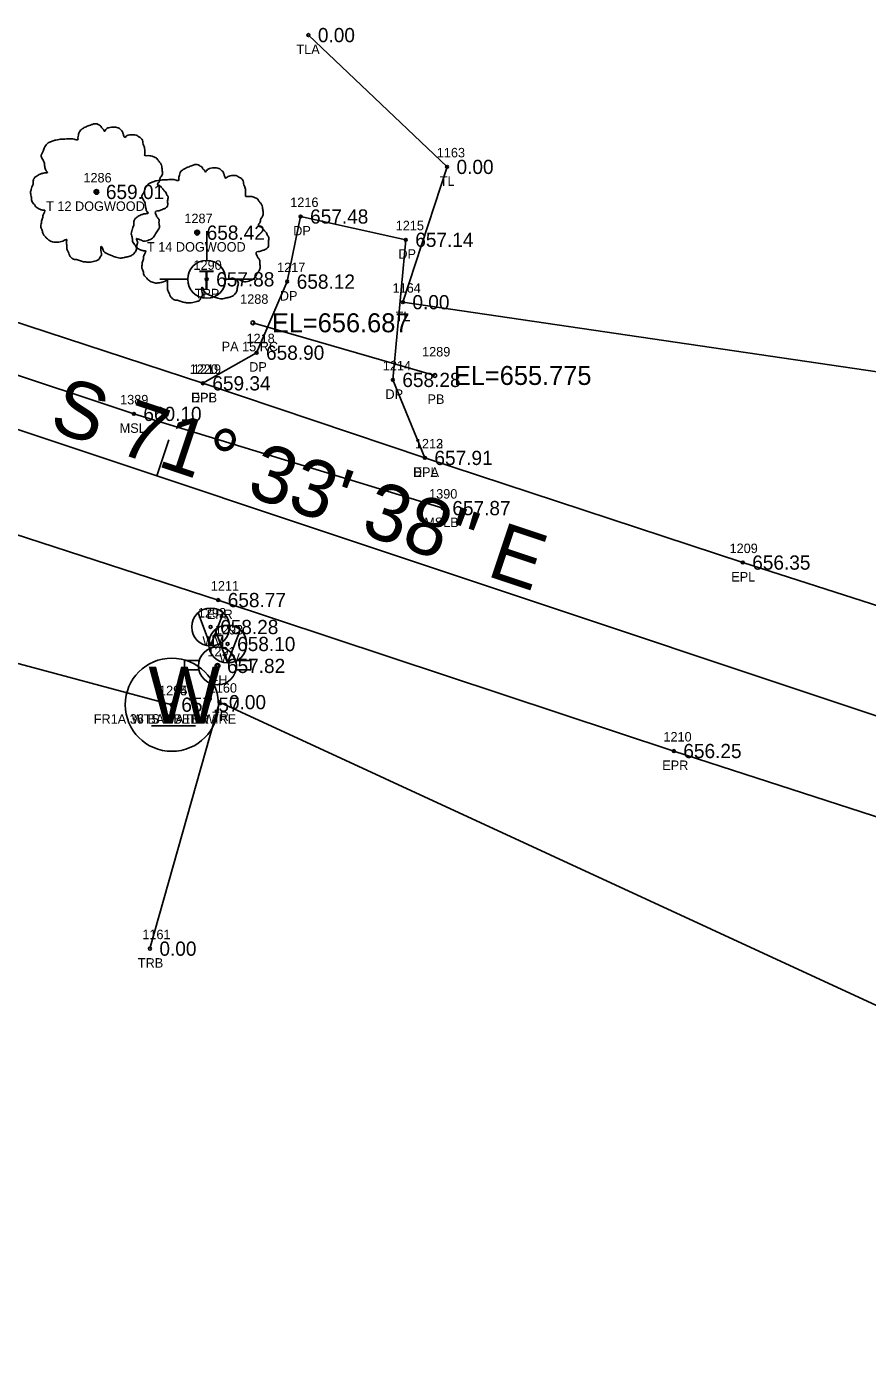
# Model space of a CAD drawing. Extents: x 1655137 to 1657928, y 1003994 to 1005407.
# Drawn here: x 1656260.6 to 1656349.2, y 1004565 to 1004705.8 of the extents above; entities that cross this region are included whole.
import ezdxf

# ---------------------------------------------------------------- set-up
doc = ezdxf.new("R2010")
doc.units = 0
for name, color, linetype in [('RD_EX_DR_Pipe', 7, 'Continuous'), ('RD_EX_DR_Pipe_txCode', 7, 'Continuous'), ('RD_EX_Driveway', 7, 'Continuous'), ('RD_EX_Driveway_txCode', 7, 'Continuous'), ('RD_EX_Fence_Other', 7, 'Continuous'), ('RD_EX_Fence_Other_txCode', 7, 'Continuous'), ('RD_EX_Misc', 7, 'Continuous'), ('RD_EX_Misc_txCode', 7, 'Continuous'), ('RD_EX_Road', 7, 'Continuous'), ('RD_EX_Road_txCode', 7, 'Continuous'), ('RD_EX_TX_Driveway_ELEV', 7, 'Continuous'), ('RD_EX_TX_Fence_Other_ELEV', 7, 'Continuous'), ('RD_EX_TX_Misc_ELEV', 7, 'Continuous'), ('RD_EX_TX_Road_ELEV', 7, 'Continuous'), ('RD_EX_TX_UT_ELEV', 7, 'Continuous'), ('RD_EX_TX_VEG_ELEV', 7, 'Continuous'), ('RD_EX_UT', 7, 'Continuous'), ('RD_EX_UT_txCode', 7, 'Continuous'), ('RD_EX_VEG', 7, 'Continuous'), ('RD_EX_VEG_txCode', 7, 'Continuous'), ('RD_HC_Cl', 7, 'Continuous'), ('RD_HC_Data', 7, 'Continuous'), ('RD_HC_Data_Tic', 7, 'Continuous'), ('RD_SMD_Locator', 7, 'Continuous'), ('RD_TX_Pipe_ElevEX', 7, 'Continuous')]:
    doc.layers.add(name, color=color, linetype=linetype)

msp = doc.modelspace()

# ---------------------------------------------------------------- linework, layer by layer
at = {"layer": 'RD_EX_DR_Pipe'}
msp.add_line((1656284.42, 1004674.61), (1656303.6, 1004669.06), dxfattribs=at)
at = {"layer": 'RD_EX_Driveway'}
msp.add_lwpolyline([(1656302.55, 1004660.37), (1656299.17, 1004668.59), (1656300.53, 1004683.36), (1656289.45, 1004685.81), (1656288.04, 1004678.95), (1656284.81, 1004671.46), (1656279.15, 1004668.23)], dxfattribs=at)
at = {"layer": 'RD_EX_Fence_Other'}
msp.add_line((1656275.88, 1004634.36), (1656245.21, 1004642.54), dxfattribs=at)
at = {"layer": 'RD_EX_Misc'}
msp.add_lwpolyline([(1655875.57, 1004783.81), (1655899.12, 1004775.73), (1655924.14, 1004767.92), (1655957.49, 1004756.44), (1655982.24, 1004748.48), (1656011.78, 1004739.5), (1656033.16, 1004732.17), (1656057.84, 1004724.63), (1656091.05, 1004714.31), (1656106.3, 1004710.84), (1656119.06, 1004707.85), (1656127.53, 1004711.03), (1656137.41, 1004709.54), (1656150.27, 1004705.03), (1656164.33, 1004699.6), (1656171.58, 1004694.85), (1656180.97, 1004693.87), (1656197.98, 1004688.49), (1656215.11, 1004682.58), (1656240.68, 1004675.39), (1656271.88, 1004665.01), (1656304.44, 1004655.08)], dxfattribs=at)
at = {"layer": 'RD_EX_Road'}
for points in [[(1656365.12, 1004639.99), (1656336.04, 1004649.34), (1656302.55, 1004660.37), (1656279.15, 1004668.23), (1656240.07, 1004681.05), (1656188.23, 1004698.03), (1656166.72, 1004705.51), (1656141.16, 1004714.06), (1656093.11, 1004730.11), (1656044.16, 1004746.75), (1655996.36, 1004762.45), (1655947.2, 1004778.68), (1655899.09, 1004794.03), (1655850.62, 1004809.99), (1655801.91, 1004826.1), (1655753.09, 1004842.31), (1655704.25, 1004858.1)], [(1656358.5, 1004619.83), (1656328.78, 1004629.48), (1656280.77, 1004645.39), (1656247.66, 1004656.11), (1656244.5, 1004656.52), (1656222.03, 1004663.57), (1656217.65, 1004665.96), (1656183.42, 1004677.32), (1656134.59, 1004693.72), (1656086.19, 1004709.75), (1656037.58, 1004726.13), (1655989.57, 1004741.99), (1655940.62, 1004757.88), (1655892.37, 1004773.61), (1655843.48, 1004789.36), (1655805.73, 1004801.4), (1655779.22, 1004810.43), (1655768.8, 1004813.1), (1655744.59, 1004822.13), (1655698.83, 1004837.65)]]:
    msp.add_lwpolyline(points, dxfattribs=at)
at = {"layer": 'RD_EX_UT'}
for p, q in [((1656279.55, 1004684.26), (1656279.55, 1004681.19)), ((1656274.62, 1004679.21), (1656277.55, 1004679.21)), ((1656281.55, 1004679.21), (1656284.62, 1004679.21)), ((1656279.97, 1004640.55), (1656278.67, 1004644.04)), ((1656279.97, 1004640.55), (1656281.29, 1004644)), ((1656280.23, 1004641.67), (1656280.23, 1004640.39)), ((1656281.23, 1004641.67), (1656280.23, 1004641.67)), ((1656281.76, 1004638.77), (1656280.46, 1004642.25)), ((1656281.23, 1004640.37), (1656281.23, 1004641.67)), ((1656281.76, 1004638.77), (1656283.08, 1004642.21)), ((1656278.77, 1004639.02), (1656277.21, 1004639.02)), ((1656277.21, 1004639.02), (1656277.21, 1004638.02)), ((1656284.21, 1004639.02), (1656282.6, 1004639.02)), ((1656284.21, 1004638.02), (1656284.21, 1004639.02)), ((1656277.21, 1004638.02), (1656278.73, 1004638.02)), ((1656282.64, 1004638.02), (1656284.21, 1004638.02)), ((1656273.75, 1004632.15), (1656278.38, 1004632.15))]:
    msp.add_line(p, q, dxfattribs=at)
for centre, radius in [((1656279.55, 1004679.19), 2), ((1656279.97, 1004642.55), 2), ((1656281.76, 1004640.76), 2), ((1656280.69, 1004638.45), 2), ((1656275.88, 1004634.36), 4.91), ((1656280.69, 1004638.45), 0.25)]:
    msp.add_circle(centre, radius, dxfattribs=at)
for start, end in [(74.2455, 103.2128), (163.3387, 192.315), (347.685, 16.6613)]:
    msp.add_arc((1656280.69, 1004638.45), 2, start, end, dxfattribs=at)
at = {"layer": 'RD_EX_VEG'}
for points in [[(1656290.27, 1004704.93), (1656304.88, 1004691.04), (1656300.23, 1004676.78), (1656393.98, 1004663.01), (1656541.61, 1004613.06), (1656540.34, 1004645.89)], [(1656891.08, 1004405.37), (1656915.13, 1004420.4), (1656763.49, 1004475.48), (1656570, 1004542.2), (1656467.82, 1004565.09), (1656367.55, 1004594.62), (1656280.9, 1004634.63), (1656273.57, 1004608.65)]]:
    msp.add_lwpolyline(points, dxfattribs=at)
for centre, radius in [((1656267.93, 1004688.4), 0.25), ((1656267.91, 1004688.38), 0.0001), ((1656278.55, 1004684.11), 0.25), ((1656278.54, 1004684.09), 0.0001)]:
    msp.add_circle(centre, radius, dxfattribs=at)
for points in [[(1656268.06, 1004695.57), (1656267.76, 1004695.59), (1656267.43, 1004695.49), (1656267.18, 1004695.39), (1656266.96, 1004695.32), (1656266.73, 1004695.22), (1656266.43, 1004695.04), (1656266.21, 1004694.84), (1656266.08, 1004694.59), (1656266.03, 1004694.37), (1656265.98, 1004694.09), (1656265.98, 1004693.92), (1656265.86, 1004693.89), (1656265.71, 1004693.92), (1656265.46, 1004693.99), (1656265.21, 1004693.99), (1656264.96, 1004693.99), (1656264.61, 1004693.97), (1656264.26, 1004693.97), (1656263.98, 1004693.92), (1656263.66, 1004693.87), (1656263.28, 1004693.74), (1656262.93, 1004693.62), (1656262.63, 1004693.37), (1656262.38, 1004692.89), (1656262.26, 1004692.54), (1656262.11, 1004692.29), (1656262.26, 1004691.84), (1656262.43, 1004691.49), (1656262.46, 1004691.29), (1656262.53, 1004690.87), (1656262.63, 1004690.64), (1656262.76, 1004690.44), (1656262.68, 1004690.42), (1656262.31, 1004690.37), (1656262.01, 1004690.27), (1656261.58, 1004690.04), (1656261.36, 1004689.82), (1656261.26, 1004689.49), (1656261.24, 1004689.14), (1656261.14, 1004688.94), (1656261.06, 1004688.67), (1656261.04, 1004688.59), (1656260.99, 1004688.27), (1656261.09, 1004687.82), (1656261.11, 1004687.47), (1656261.24, 1004687.24), (1656261.39, 1004687.07), (1656261.56, 1004686.82), (1656261.96, 1004686.59), (1656262.28, 1004686.49), (1656262.48, 1004686.47), (1656262.31, 1004685.97), (1656262.26, 1004685.62), (1656262.13, 1004685.22), (1656262.13, 1004685.15), (1656262.08, 1004684.67), (1656262.23, 1004684.35), (1656262.31, 1004683.97), (1656262.48, 1004683.75), (1656262.76, 1004683.45), (1656263.08, 1004683.22), (1656263.58, 1004683.1), (1656263.98, 1004683.12), (1656264.56, 1004683.3), (1656264.81, 1004683.37), (1656264.78, 1004683.2), (1656264.81, 1004682.82), (1656264.81, 1004682.4), (1656264.96, 1004682.07), (1656265.06, 1004681.8), (1656265.21, 1004681.55), (1656265.53, 1004681.32), (1656265.93, 1004681.25), (1656266.36, 1004681.1), (1656266.81, 1004681.02), (1656267.31, 1004681), (1656267.91, 1004681.15), (1656268.18, 1004681.27), (1656268.28, 1004681.45), (1656268.48, 1004681.82), (1656268.43, 1004682.05), (1656268.46, 1004682.65), (1656268.56, 1004682.47), (1656268.73, 1004682.12), (1656269.23, 1004681.82), (1656269.63, 1004681.65), (1656270.11, 1004681.5), (1656270.41, 1004681.42), (1656270.88, 1004681.5), (1656271.26, 1004681.57), (1656271.63, 1004681.7), (1656271.93, 1004681.97), (1656272.11, 1004682.25), (1656272.16, 1004682.52), (1656272.23, 1004682.9), (1656272.28, 1004683.07)], [(1656272.28, 1004683.07), (1656272.21, 1004683.25), (1656272.16, 1004683.5), (1656272.23, 1004683.47), (1656272.41, 1004683.42), (1656272.68, 1004683.3), (1656272.91, 1004683.22), (1656273.23, 1004683.25), (1656273.5, 1004683.35), (1656273.95, 1004683.62), (1656274.23, 1004684.1), (1656274.5, 1004684.5), (1656274.58, 1004684.82), (1656274.53, 1004685.05), (1656274.5, 1004685.54), (1656274.3, 1004685.79), (1656274.25, 1004685.92), (1656274.15, 1004686.32), (1656274.23, 1004686.37), (1656274.5, 1004686.42), (1656274.88, 1004686.54), (1656275.15, 1004686.67), (1656275.38, 1004686.84), (1656275.45, 1004687.07), (1656275.43, 1004687.47), (1656275.48, 1004687.87), (1656275.4, 1004688.02), (1656275.3, 1004688.17), (1656275.23, 1004688.37), (1656275.08, 1004688.52), (1656274.98, 1004688.67), (1656274.88, 1004688.77), (1656274.75, 1004688.92), (1656274.58, 1004689.04), (1656274.43, 1004689.09), (1656274.38, 1004689.24), (1656274.53, 1004689.44), (1656274.58, 1004689.54), (1656274.6, 1004689.77), (1656274.83, 1004690.12), (1656274.88, 1004690.52), (1656274.83, 1004690.94), (1656274.78, 1004691.22), (1656274.63, 1004691.49), (1656274.43, 1004691.74), (1656274.3, 1004691.92), (1656274.13, 1004692.04), (1656273.8, 1004692.17), (1656273.55, 1004692.22), (1656273.2, 1004692.22), (1656273, 1004692.27), (1656273.03, 1004692.32), (1656273.03, 1004692.47), (1656273.03, 1004692.74), (1656272.95, 1004693.19), (1656272.81, 1004693.69), (1656272.81, 1004693.72), (1656272.71, 1004693.97), (1656272.48, 1004694.17), (1656272.31, 1004694.27), (1656272.11, 1004694.39), (1656271.86, 1004694.42), (1656271.56, 1004694.42), (1656271.28, 1004694.37), (1656271.08, 1004694.27), (1656270.91, 1004694.14), (1656270.83, 1004694.29), (1656270.73, 1004694.59), (1656270.68, 1004694.74), (1656270.53, 1004694.92), (1656270.31, 1004695.12), (1656269.86, 1004695.24), (1656269.23, 1004695.17), (1656268.93, 1004694.97), (1656268.78, 1004694.79), (1656268.73, 1004694.92), (1656268.53, 1004695.12), (1656268.43, 1004695.29), (1656268.26, 1004695.42), (1656268.11, 1004695.52), (1656268.01, 1004695.57)], [(1656278.68, 1004691.27), (1656278.38, 1004691.3), (1656278.06, 1004691.2), (1656277.81, 1004691.1), (1656277.58, 1004691.02), (1656277.36, 1004690.92), (1656277.06, 1004690.75), (1656276.83, 1004690.55), (1656276.71, 1004690.3), (1656276.66, 1004690.07), (1656276.61, 1004689.8), (1656276.61, 1004689.63), (1656276.48, 1004689.6), (1656276.33, 1004689.63), (1656276.08, 1004689.7), (1656275.83, 1004689.7), (1656275.58, 1004689.7), (1656275.23, 1004689.68), (1656274.88, 1004689.68), (1656274.61, 1004689.63), (1656274.28, 1004689.58), (1656273.91, 1004689.45), (1656273.56, 1004689.33), (1656273.26, 1004689.08), (1656273.01, 1004688.6), (1656272.88, 1004688.25), (1656272.73, 1004688), (1656272.88, 1004687.55), (1656273.06, 1004687.2), (1656273.08, 1004687), (1656273.16, 1004686.58), (1656273.26, 1004686.35), (1656273.38, 1004686.15), (1656273.31, 1004686.13), (1656272.93, 1004686.08), (1656272.63, 1004685.98), (1656272.21, 1004685.75), (1656271.98, 1004685.53), (1656271.88, 1004685.2), (1656271.86, 1004684.85), (1656271.76, 1004684.65), (1656271.69, 1004684.38), (1656271.66, 1004684.3), (1656271.61, 1004683.98), (1656271.71, 1004683.53), (1656271.74, 1004683.18), (1656271.86, 1004682.95), (1656272.01, 1004682.78), (1656272.18, 1004682.53), (1656272.58, 1004682.3), (1656272.91, 1004682.2), (1656273.11, 1004682.18), (1656272.93, 1004681.68), (1656272.88, 1004681.33), (1656272.76, 1004680.93), (1656272.76, 1004680.85), (1656272.71, 1004680.38), (1656272.86, 1004680.05), (1656272.93, 1004679.68), (1656273.11, 1004679.45), (1656273.38, 1004679.15), (1656273.71, 1004678.93), (1656274.21, 1004678.8), (1656274.61, 1004678.83), (1656275.18, 1004679), (1656275.43, 1004679.08), (1656275.41, 1004678.9), (1656275.43, 1004678.53), (1656275.43, 1004678.11), (1656275.58, 1004677.78), (1656275.68, 1004677.51), (1656275.83, 1004677.26), (1656276.16, 1004677.03), (1656276.56, 1004676.96), (1656276.98, 1004676.81), (1656277.43, 1004676.73), (1656277.93, 1004676.71), (1656278.53, 1004676.86), (1656278.81, 1004676.98), (1656278.91, 1004677.16), (1656279.11, 1004677.53), (1656279.06, 1004677.76), (1656279.08, 1004678.36), (1656279.18, 1004678.18), (1656279.36, 1004677.83), (1656279.86, 1004677.53), (1656280.26, 1004677.36), (1656280.73, 1004677.21), (1656281.03, 1004677.13), (1656281.51, 1004677.21), (1656281.88, 1004677.28), (1656282.26, 1004677.41), (1656282.56, 1004677.68), (1656282.73, 1004677.96), (1656282.78, 1004678.23), (1656282.86, 1004678.6), (1656282.91, 1004678.78)], [(1656282.91, 1004678.78), (1656282.83, 1004678.95), (1656282.78, 1004679.2), (1656282.86, 1004679.18), (1656283.03, 1004679.13), (1656283.3, 1004679), (1656283.53, 1004678.93), (1656283.85, 1004678.95), (1656284.13, 1004679.05), (1656284.58, 1004679.33), (1656284.85, 1004679.8), (1656285.13, 1004680.2), (1656285.2, 1004680.53), (1656285.15, 1004680.75), (1656285.13, 1004681.25), (1656284.93, 1004681.5), (1656284.88, 1004681.63), (1656284.78, 1004682.03), (1656284.85, 1004682.08), (1656285.13, 1004682.13), (1656285.5, 1004682.25), (1656285.78, 1004682.38), (1656286, 1004682.55), (1656286.08, 1004682.78), (1656286.05, 1004683.18), (1656286.1, 1004683.58), (1656286.03, 1004683.73), (1656285.93, 1004683.88), (1656285.85, 1004684.08), (1656285.7, 1004684.23), (1656285.6, 1004684.38), (1656285.5, 1004684.48), (1656285.38, 1004684.63), (1656285.2, 1004684.75), (1656285.05, 1004684.8), (1656285, 1004684.95), (1656285.15, 1004685.15), (1656285.2, 1004685.25), (1656285.23, 1004685.48), (1656285.45, 1004685.83), (1656285.5, 1004686.23), (1656285.45, 1004686.65), (1656285.4, 1004686.93), (1656285.25, 1004687.2), (1656285.05, 1004687.45), (1656284.93, 1004687.63), (1656284.75, 1004687.75), (1656284.43, 1004687.88), (1656284.18, 1004687.93), (1656283.83, 1004687.93), (1656283.63, 1004687.98), (1656283.65, 1004688.03), (1656283.65, 1004688.18), (1656283.65, 1004688.45), (1656283.58, 1004688.9), (1656283.43, 1004689.4), (1656283.43, 1004689.43), (1656283.33, 1004689.68), (1656283.11, 1004689.88), (1656282.93, 1004689.97), (1656282.73, 1004690.1), (1656282.48, 1004690.12), (1656282.18, 1004690.12), (1656281.91, 1004690.07), (1656281.71, 1004689.97), (1656281.53, 1004689.85), (1656281.46, 1004690), (1656281.36, 1004690.3), (1656281.31, 1004690.45), (1656281.16, 1004690.62), (1656280.93, 1004690.82), (1656280.48, 1004690.95), (1656279.86, 1004690.87), (1656279.56, 1004690.67), (1656279.41, 1004690.5), (1656279.36, 1004690.62), (1656279.16, 1004690.82), (1656279.06, 1004691), (1656278.88, 1004691.12), (1656278.73, 1004691.22), (1656278.63, 1004691.27)]]:
    msp.add_spline(points, degree=3, dxfattribs=at)
at = {"layer": 'RD_HC_Cl'}
msp.add_line((1656069.26, 1004726.84), (1656507.36, 1004580.77), dxfattribs=at)
at = {"layer": 'RD_HC_Data_Tic'}
msp.add_line((1656274.3, 1004658.47), (1656275.57, 1004662.27), dxfattribs=at)
at = {"layer": 'RD_SMD_Locator'}
for centre, radius in [((1656290.27, 1004704.93), 0.15), ((1656304.88, 1004691.04), 0.15), ((1656267.93, 1004688.4), 0.15), ((1656289.45, 1004685.81), 0.15), ((1656278.55, 1004684.11), 0.15), ((1656300.53, 1004683.36), 0.15), ((1656279.55, 1004679.19), 0.15), ((1656288.04, 1004678.95), 0.15), ((1656300.23, 1004676.78), 0.15), ((1656284.42, 1004674.61), 0.2), ((1656284.81, 1004671.46), 0.15), ((1656279.15, 1004668.23), 0.15), ((1656279.15, 1004668.23), 0.15), ((1656299.17, 1004668.59), 0.15), ((1656303.6, 1004669.06), 0.2), ((1656271.88, 1004665.01), 0.15), ((1656302.55, 1004660.37), 0.15), ((1656302.55, 1004660.37), 0.15), ((1656304.44, 1004655.08), 0.15), ((1656336.04, 1004649.34), 0.15), ((1656280.77, 1004645.39), 0.15), ((1656279.97, 1004642.55), 0.15), ((1656281.76, 1004640.76), 0.15), ((1656280.69, 1004638.45), 0.15), ((1656275.88, 1004634.36), 0.15), ((1656275.88, 1004634.36), 0.15), ((1656280.9, 1004634.63), 0.15), ((1656328.78, 1004629.48), 0.15), ((1656273.57, 1004608.65), 0.15)]:
    msp.add_circle(centre, radius, dxfattribs=at)

# ---------------------------------------------------------------- texts
at = {"layer": 'RD_EX_DR_Pipe_txCode'}
for s, p in [('1288', (1656283.08, 1004676.61)), ('PA 15 RC', (1656281.13, 1004671.61)), ('1289', (1656302.25, 1004671.06)), ('PB', (1656302.82, 1004666.06))]:
    msp.add_text(s, height=1, dxfattribs=at).set_placement(p)
at = {"layer": 'RD_EX_Driveway_txCode'}
for s, p in [('1216', (1656288.36, 1004686.81)), ('1215', (1656299.47, 1004684.36)), ('DP', (1656288.67, 1004683.81)), ('DP', (1656299.75, 1004681.36)), ('1217', (1656286.97, 1004679.95)), ('DP', (1656287.26, 1004676.95)), ('1218', (1656283.75, 1004672.46)), ('1219', (1656278.09, 1004669.23)), ('DP', (1656284.03, 1004669.46)), ('1214', (1656298.11, 1004669.59)), ('DPB', (1656277.9, 1004666.23)), ('DP', (1656298.39, 1004666.59)), ('1213', (1656301.49, 1004661.37)), ('DPA', (1656301.28, 1004658.37))]:
    msp.add_text(s, height=1, dxfattribs=at).set_placement(p)
at = {"layer": 'RD_EX_Fence_Other_txCode'}
for s, p in [('1295', (1656274.53, 1004635.36)), ('FR1A 36 BARBED WIRE', (1656267.65, 1004632.36))]:
    msp.add_text(s, height=1, dxfattribs=at).set_placement(p)
at = {"layer": 'RD_EX_Misc_txCode'}
for s, p in [('1389', (1656270.43, 1004666.01)), ('MSL', (1656270.38, 1004663.01)), ('1390', (1656302.99, 1004656.08)), ('MSLB', (1656302.47, 1004653.08))]:
    msp.add_text(s, height=1, dxfattribs=at).set_placement(p)
at = {"layer": 'RD_EX_Road_txCode'}
for s, p in [('1220', (1656277.76, 1004669.23)), ('EPL', (1656277.94, 1004666.23)), ('1212', (1656301.49, 1004661.37)), ('EPL', (1656301.35, 1004658.37)), ('1209', (1656334.65, 1004650.34)), ('1211', (1656279.99, 1004646.39)), ('EPL', (1656334.83, 1004647.34)), ('EPR', (1656279.55, 1004643.39)), ('1210', (1656327.68, 1004630.48)), ('EPR', (1656327.56, 1004627.48))]:
    msp.add_text(s, height=1, dxfattribs=at).set_placement(p)
at = {"layer": 'RD_EX_TX_Driveway_ELEV'}
for s, p in [('657.48', (1656290.45, 1004685.06)), ('657.14', (1656301.53, 1004682.61)), ('658.12', (1656289.04, 1004678.2)), ('658.90', (1656285.81, 1004670.71)), ('659.34', (1656280.15, 1004667.48)), ('658.28', (1656300.17, 1004667.84)), ('657.91', (1656303.55, 1004659.62))]:
    msp.add_text(s, height=1.5, dxfattribs=at).set_placement(p)
at = {"layer": 'RD_EX_TX_Fence_Other_ELEV'}
msp.add_text('657.57', height=1.5, dxfattribs=at).set_placement((1656276.88, 1004633.61))
at = {"layer": 'RD_EX_TX_Misc_ELEV'}
for s, p in [('660.10', (1656272.88, 1004664.26)), ('657.87', (1656305.44, 1004654.33))]:
    msp.add_text(s, height=1.5, dxfattribs=at).set_placement(p)
at = {"layer": 'RD_EX_TX_Road_ELEV'}
for s, p in [('659.34', (1656280.15, 1004667.48)), ('657.91', (1656303.55, 1004659.62)), ('656.35', (1656337.04, 1004648.59)), ('658.77', (1656281.77, 1004644.64)), ('656.25', (1656329.78, 1004628.73))]:
    msp.add_text(s, height=1.5, dxfattribs=at).set_placement(p)
at = {"layer": 'RD_EX_TX_UT_ELEV'}
for s, p in [('657.88', (1656280.55, 1004678.44)), ('658.28', (1656280.97, 1004641.8)), ('658.10', (1656282.76, 1004640.01)), ('657.82', (1656281.69, 1004637.7)), ('657.57', (1656276.88, 1004633.61))]:
    msp.add_text(s, height=1.5, dxfattribs=at).set_placement(p)
at = {"layer": 'RD_EX_TX_VEG_ELEV'}
for s, p in [('0.00', (1656291.27, 1004704.18)), ('0.00', (1656305.88, 1004690.29)), ('659.01', (1656268.93, 1004687.65)), ('658.42', (1656279.55, 1004683.36)), ('0.00', (1656301.23, 1004676.03)), ('0.00', (1656281.9, 1004633.88)), ('0.00', (1656274.57, 1004607.9))]:
    msp.add_text(s, height=1.5, dxfattribs=at).set_placement(p)
at = {"layer": 'RD_EX_UT'}
for s, height, p in [('T', 2, (1656278.7, 1004678.15)), ('W', 6, (1656273.41, 1004632.36))]:
    msp.add_text(s, height=height, dxfattribs=at).set_placement(p)
at = {"layer": 'RD_EX_UT_txCode'}
for s, p in [('1290', (1656278.16, 1004680.19)), ('TPP', (1656278.28, 1004677.19)), ('1292', (1656278.62, 1004643.55)), ('1293', (1656280.41, 1004641.76)), ('WV', (1656279.11, 1004640.55)), ('1291', (1656279.62, 1004639.45)), ('WV', (1656280.9, 1004638.76)), ('FH', (1656279.96, 1004636.45)), ('1294', (1656274.53, 1004635.36)), ('WTS WATER', (1656271.64, 1004632.36))]:
    msp.add_text(s, height=1, dxfattribs=at).set_placement(p)
at = {"layer": 'RD_EX_VEG_txCode'}
for s, p in [('TLA', (1656289.01, 1004702.93)), ('1163', (1656303.8, 1004692.04)), ('1286', (1656266.56, 1004689.4)), ('TL', (1656304.11, 1004689.04)), ('T 12 DOGWOOD', (1656262.63, 1004686.4)), ('1287', (1656277.2, 1004685.11)), ('T 14 DOGWOOD', (1656273.26, 1004682.11)), ('1164', (1656299.14, 1004677.78)), ('TL', (1656299.46, 1004674.78)), ('1160', (1656279.77, 1004635.63)), ('TR', (1656280.1, 1004632.63)), ('1161', (1656272.77, 1004609.65)), ('TRB', (1656272.3, 1004606.65))]:
    msp.add_text(s, height=1, dxfattribs=at).set_placement(p)
at = {"layer": 'RD_HC_Data'}
msp.add_text('S 71%%d 33\' 38" E', height=6, rotation=341.5604, dxfattribs=at).set_placement((1656262.78, 1004663.37))
at = {"layer": 'RD_TX_Pipe_ElevEX'}
for s, p in [('EL=656.687', (1656286.42, 1004673.61)), ('EL=655.775', (1656305.6, 1004668.06))]:
    msp.add_text(s, height=2, dxfattribs=at).set_placement(p)

doc.saveas('drawing.dxf')
